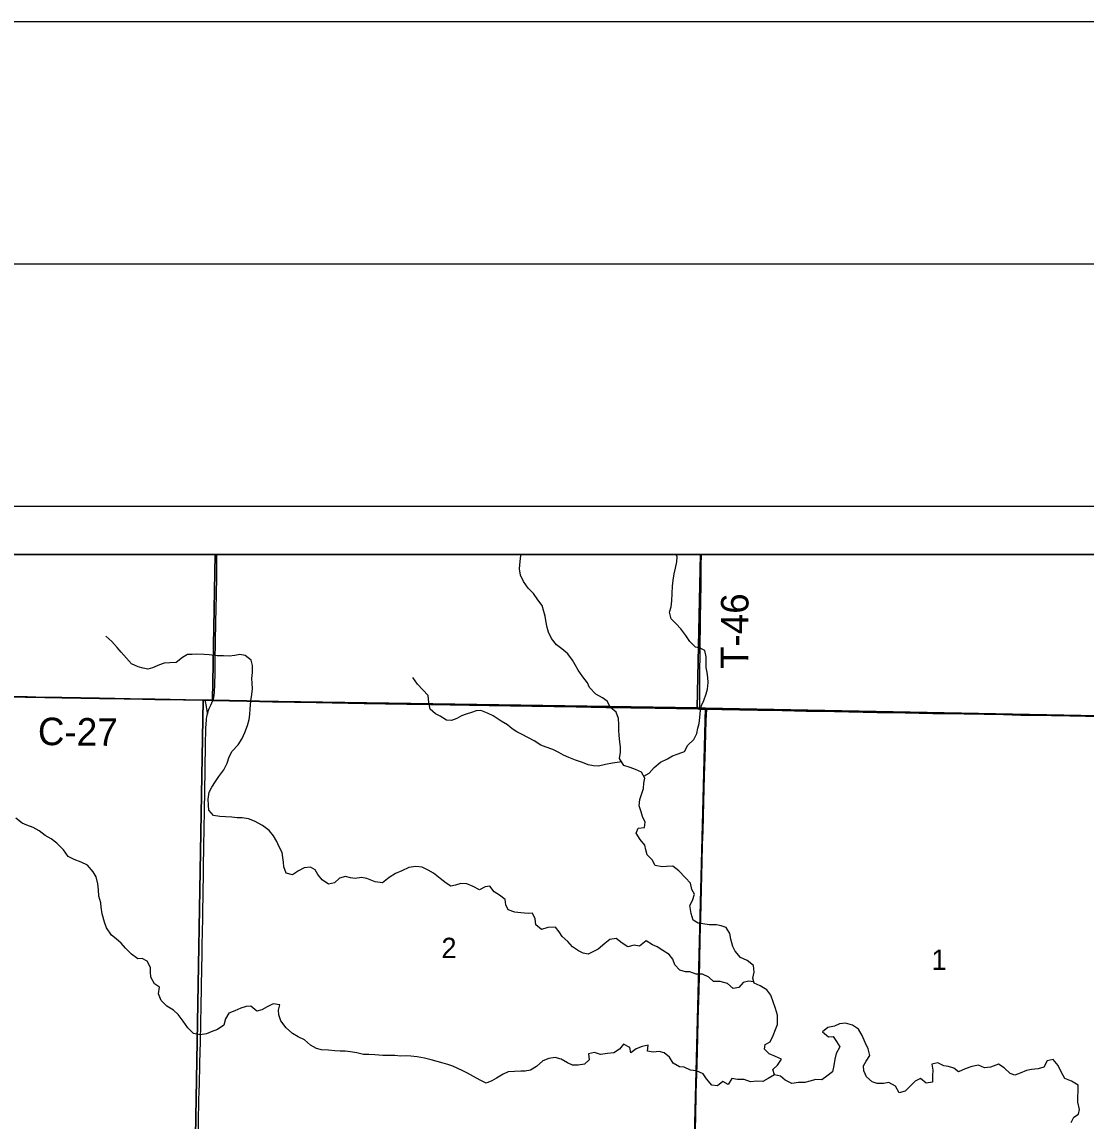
# Model space of a CAD drawing. Extents: x 0 to 34, y 0 to 22.
# Drawn here: x 3.417 to 5.615, y 19.729 to 22 of the extents above; entities that cross this region are included whole.
import ezdxf

# ---------------------------------------------------------------- set-up
doc = ezdxf.new("R2010")
doc.units = 0
for name, color, linetype in [('GM_X_Corporation', 7, 'Continuous'), ('GM_X_County_Road', 7, 'Continuous'), ('GM_X_County_Road_Text', 7, 'Continuous'), ('GM_X_Minor_River', 7, 'Continuous'), ('GM_X_Section_Text', 7, 'Continuous'), ('GM_X_State_Route', 7, 'Continuous'), ('GM_X_Township_Road', 7, 'Continuous'), ('GM_X_Township_Road_Text', 7, 'Continuous'), ('SH_Border', 7, 'Continuous'), ('SH_Cut_Line', 7, 'Continuous'), ('SH_Data', 7, 'Continuous')]:
    doc.layers.add(name, color=color, linetype=linetype)

msp = doc.modelspace()

# ---------------------------------------------------------------- linework, layer by layer
at = {"layer": 'GM_X_Corporation'}
for points in [[(8.9, 20.9), (2.1, 20.9), (2.1, 14.6217)], [(5.8292, 20.9), (2.1, 20.9)], [(5.742, 20.5637), (5.5822, 20.5668), (5.5443, 20.5675), (5.4809, 20.5688), (5.4448, 20.5696), (5.364, 20.5708), (5.2987, 20.5721), (5.2415, 20.573), (5.1837, 20.5739), (5.096, 20.5757), (5.0369, 20.5768), (4.9878, 20.5778), (4.9369, 20.5789), (4.8629, 20.5803), (4.8315, 20.5809), (4.8169, 20.5812), (4.8131, 20.5812), (4.7249, 20.583), (4.6236, 20.5845), (4.562, 20.5855), (4.47, 20.5869), (4.3823, 20.5883), (4.2611, 20.5904), (4.212, 20.5911), (4.1237, 20.5925), (4.0249, 20.5943), (3.9341, 20.5961), (3.8813, 20.5975), (3.8459, 20.5982), (3.8113, 20.5988), (3.7944, 20.5991), (3.7547, 20.5998), (3.6913, 20.6008), (3.6403, 20.6019), (3.5769, 20.6028), (3.4992, 20.6043), (3.4644, 20.6047), (3.4277, 20.6055), (3.3867, 20.6062)], [(3.3867, 20.6062), (3.4277, 20.6055), (3.4644, 20.6047), (3.4992, 20.6043), (3.5769, 20.6028), (3.6403, 20.6019), (3.6913, 20.6008), (3.7547, 20.5998), (3.7944, 20.5991), (3.8113, 20.5988), (3.8459, 20.5982), (3.8813, 20.5975), (3.9341, 20.5961), (4.0249, 20.5943), (4.1237, 20.5925), (4.212, 20.5911), (4.2611, 20.5904), (4.3823, 20.5883), (4.47, 20.5869), (4.562, 20.5855), (4.6236, 20.5845), (4.7249, 20.583), (4.8131, 20.5812), (4.8169, 20.5812), (4.8315, 20.5809), (4.8629, 20.5803), (4.9369, 20.5789), (4.9878, 20.5778), (5.0369, 20.5768), (5.096, 20.5757), (5.1837, 20.5739), (5.2415, 20.573), (5.2987, 20.5721), (5.364, 20.5708), (5.4448, 20.5696), (5.4809, 20.5688), (5.5443, 20.5675), (5.5822, 20.5668), (5.742, 20.5637)]]:
    msp.add_lwpolyline(points, dxfattribs=at)
for points in [[(3.8162, 20.9), (2.8176, 20.9), (2.8121, 20.6157), (3.7914, 20.5987), (3.8107, 20.5986)], [(4.8189, 20.9), (3.8162, 20.9), (3.8107, 20.5986), (4.8123, 20.5837)], [(5.8254, 20.9), (4.8189, 20.9), (4.8123, 20.5837), (4.829, 20.5833), (5.8164, 20.5638)], [(2.7647, 20.6164), (2.8121, 20.6157), (3.7914, 20.5987), (3.7742, 19.6197), (2.7554, 19.6589)], [(3.7914, 20.5987), (3.8107, 20.5986), (4.8123, 20.5837), (4.829, 20.5833), (4.8036, 19.5906), (3.7742, 19.6197)], [(4.829, 20.5833), (5.8164, 20.5638), (5.7981, 19.5979), (5.7974, 19.5584), (4.8036, 19.5906)]]:
    msp.add_lwpolyline(points, close=True, dxfattribs=at)
at = {"layer": 'GM_X_County_Road'}
for p, q in [((3.7946, 20.5986), (3.8116, 20.5982)), ((4.8171, 20.5806), (4.8317, 20.5803))]:
    msp.add_line(p, q, dxfattribs=at)
for points in [[(2.8134, 20.6157), (2.8344, 20.6154), (2.8729, 20.6147), (2.9127, 20.614), (2.963, 20.613), (3.0221, 20.6119), (3.0587, 20.6113), (3.1141, 20.6101), (3.1501, 20.6096), (3.216, 20.6086), (3.2614, 20.6078), (3.308, 20.6069), (3.3397, 20.6062), (3.3869, 20.6056), (3.428, 20.605), (3.4646, 20.6042), (3.4994, 20.6037), (3.5771, 20.6023), (3.6406, 20.6013), (3.6915, 20.6002), (3.7549, 20.5993), (3.7946, 20.5986)], [(3.7946, 20.5986), (3.7956, 20.5958), (3.7964, 20.5929), (3.797, 20.5897), (3.7976, 20.5853), (3.7982, 20.581), (3.7989, 20.577), (3.7998, 20.5728), (3.8004, 20.5705)], [(3.8116, 20.5982), (3.8461, 20.5977), (3.8816, 20.5969), (3.9344, 20.5955), (4.0251, 20.5937), (4.124, 20.592), (4.2122, 20.5906), (4.2613, 20.5898), (4.3826, 20.5877), (4.4702, 20.5863), (4.5622, 20.5849), (4.6238, 20.584), (4.7251, 20.5824), (4.8134, 20.5807), (4.8171, 20.5806)], [(4.8065, 19.6437), (4.8092, 19.7375), (4.8101, 19.7872), (4.8118, 19.8469), (4.8135, 19.9014), (4.8144, 19.9387), (4.8161, 19.9996), (4.8174, 20.0592), (4.8185, 20.1071), (4.8193, 20.1456), (4.8202, 20.1791), (4.8218, 20.2375), (4.8224, 20.2642), (4.8233, 20.3009), (4.8241, 20.3288), (4.826, 20.3891), (4.8275, 20.4425), (4.8283, 20.4817), (4.829, 20.5034), (4.8298, 20.5302), (4.8307, 20.5562), (4.8312, 20.5686), (4.8317, 20.5803)], [(4.8317, 20.5803), (4.8631, 20.5797), (4.9371, 20.5783), (4.9881, 20.5772), (5.0372, 20.5763), (5.0962, 20.5752), (5.1839, 20.5733), (5.2417, 20.5725), (5.2989, 20.5715), (5.3642, 20.5703), (5.445, 20.5691), (5.4811, 20.5682), (5.5445, 20.5669), (5.5824, 20.5662), (5.7422, 20.5631), (5.7721, 20.5624), (5.8193, 20.5613)]]:
    msp.add_lwpolyline(points, dxfattribs=at)
at = {"layer": 'GM_X_Minor_River'}
for points in [[(4.4629, 20.8304), (4.453, 20.8443), (4.4472, 20.8574), (4.4452, 20.87), (4.446, 20.8852), (4.4474, 20.8977), (4.4477, 20.9)], [(4.7019, 20.4418), (4.713, 20.4481), (4.7232, 20.46), (4.7364, 20.4707), (4.751, 20.4775), (4.7614, 20.4841), (4.7729, 20.488), (4.7859, 20.493), (4.793, 20.5061), (4.8051, 20.5179), (4.8111, 20.5303), (4.8136, 20.5409), (4.8161, 20.5507), (4.8176, 20.5628), (4.8191, 20.578), (4.8212, 20.5878), (4.8257, 20.5983), (4.8306, 20.6119), (4.8331, 20.6217), (4.8345, 20.6354), (4.8344, 20.6456), (4.8324, 20.6563), (4.8308, 20.6662), (4.8306, 20.6761), (4.8309, 20.6883), (4.8278, 20.7016), (4.8181, 20.706), (4.8083, 20.7082), (4.7972, 20.7199), (4.7887, 20.7322), (4.7784, 20.7462), (4.7677, 20.7571), (4.7585, 20.7668), (4.7546, 20.7806), (4.7583, 20.7919), (4.7594, 20.804), (4.7605, 20.8192), (4.7613, 20.8344), (4.7623, 20.8469), (4.7642, 20.8597), (4.7671, 20.8714), (4.7701, 20.885), (4.7704, 20.8953), (4.7685, 20.9)], [(4.9721, 19.8246), (4.9682, 19.8358), (4.9779, 19.8446), (4.9866, 19.857), (4.9742, 19.8626), (4.961, 19.8682), (4.951, 19.8776), (4.9528, 19.8874), (4.9628, 19.8929), (4.9692, 19.9064), (4.9737, 19.9188), (4.9781, 19.929), (4.9783, 19.9388), (4.9778, 19.9483), (4.9736, 19.9617), (4.9694, 19.9759), (4.964, 19.9897), (4.9559, 20.0002), (4.9425, 20.0089), (4.9297, 20.0145), (4.9273, 20.0244), (4.9295, 20.0369), (4.9287, 20.0506), (4.9153, 20.0612), (4.9014, 20.0673), (4.8907, 20.0804), (4.8856, 20.0901), (4.8815, 20.105), (4.8795, 20.1168), (4.8722, 20.1295), (4.8616, 20.1325), (4.8518, 20.1346), (4.8367, 20.135), (4.8238, 20.1368), (4.814, 20.1382), (4.8039, 20.1445), (4.7996, 20.1579), (4.797, 20.1747), (4.8026, 20.1852), (4.8067, 20.198), (4.8009, 20.2077), (4.7982, 20.2207), (4.7882, 20.2319), (4.7745, 20.2463), (4.7618, 20.2558), (4.7489, 20.2553), (4.7394, 20.2544), (4.7254, 20.2574), (4.7193, 20.269), (4.7089, 20.2795), (4.7057, 20.2898), (4.7041, 20.2994), (4.6945, 20.311), (4.6861, 20.3238), (4.6901, 20.3343), (4.7031, 20.3359), (4.7049, 20.3468), (4.6991, 20.3584), (4.6966, 20.3679), (4.6924, 20.3806), (4.6935, 20.3935), (4.698, 20.4063), (4.7013, 20.4161), (4.7015, 20.4275), (4.7041, 20.438), (4.6972, 20.45), (4.6848, 20.4556), (4.6739, 20.4597), (4.6607, 20.4638), (4.6519, 20.4785), (4.6534, 20.4917), (4.6537, 20.5024), (4.6524, 20.5123), (4.6508, 20.5264), (4.6503, 20.5359), (4.6502, 20.5488), (4.6498, 20.561), (4.6448, 20.574), (4.6329, 20.5838), (4.626, 20.5969), (4.6163, 20.604), (4.6028, 20.6115), (4.5895, 20.6251), (4.5852, 20.6347), (4.5756, 20.6471), (4.5661, 20.6611), (4.5603, 20.6718), (4.5545, 20.6815), (4.5449, 20.6943), (4.5326, 20.7048), (4.5215, 20.7131), (4.5112, 20.7263), (4.505, 20.7393), (4.5022, 20.7493), (4.5002, 20.7592), (4.4979, 20.7726), (4.4954, 20.7821), (4.4916, 20.7944), (4.4828, 20.806), (4.4736, 20.8195), (4.4629, 20.8304)], [(3.8504, 20.3568), (3.8372, 20.3579), (3.8258, 20.3585), (3.8129, 20.3607), (3.803, 20.3716), (3.8025, 20.3819), (3.8016, 20.3945), (3.8035, 20.4085), (3.8091, 20.419), (3.8169, 20.4309), (3.8236, 20.441), (3.8342, 20.4548), (3.841, 20.4687), (3.8448, 20.4815), (3.8515, 20.4935), (3.864, 20.5065), (3.8719, 20.5196), (3.8775, 20.532), (3.8828, 20.5467), (3.8865, 20.5591), (3.8875, 20.569), (3.8882, 20.58), (3.8897, 20.5978), (3.892, 20.6103), (3.8934, 20.622), (3.8929, 20.6338), (3.892, 20.6433), (3.8931, 20.6558), (3.893, 20.6703), (3.8903, 20.6814), (3.878, 20.6912), (3.867, 20.6933), (3.8568, 20.6913), (3.8453, 20.6897), (3.8332, 20.6904), (3.8203, 20.6907), (3.8036, 20.6923), (3.7934, 20.6933), (3.7786, 20.694), (3.7688, 20.6935), (3.7589, 20.6934), (3.7489, 20.6872), (3.7353, 20.6769), (3.7224, 20.6757), (3.7106, 20.6756), (3.7011, 20.672), (3.6869, 20.6659), (3.6769, 20.6631), (3.6671, 20.6649), (3.6569, 20.6674), (3.6434, 20.6742), (3.6331, 20.6859), (3.622, 20.6983), (3.6139, 20.708), (3.6028, 20.7204), (3.5905, 20.731)], [(4.6563, 20.4712), (4.6373, 20.4686), (4.6224, 20.4659), (4.6083, 20.4628), (4.5977, 20.4631), (4.5871, 20.4653), (4.5754, 20.4701), (4.5608, 20.4747), (4.5469, 20.4807), (4.5356, 20.4855), (4.5259, 20.4907), (4.5135, 20.4967), (4.4999, 20.5016), (4.489, 20.5061), (4.4752, 20.5148), (4.4636, 20.5208), (4.4494, 20.5287), (4.4396, 20.5335), (4.4299, 20.5399), (4.4202, 20.5481), (4.4071, 20.5556), (4.3907, 20.5663), (4.3787, 20.5719), (4.3652, 20.5776), (4.3557, 20.577), (4.3457, 20.5735), (4.335, 20.57), (4.3254, 20.5668), (4.3154, 20.5609), (4.3047, 20.557), (4.2941, 20.5573), (4.281, 20.566), (4.2713, 20.5708), (4.2601, 20.5806), (4.2578, 20.5939), (4.2563, 20.6084), (4.2341, 20.6317), (4.2249, 20.646)], [(3.7398, 19.9492), (3.7302, 19.9586), (3.716, 19.9669), (3.7049, 19.9786), (3.6991, 19.992), (3.7014, 20.0057), (3.6905, 20.0128), (3.6829, 20.0263), (3.6828, 20.0373), (3.6826, 20.0468), (3.6757, 20.0599), (3.6656, 20.0651), (3.6561, 20.0645), (3.6435, 20.074), (3.6309, 20.0864), (3.622, 20.0969), (3.6116, 20.1055), (3.6019, 20.1134), (3.5913, 20.1285), (3.5874, 20.1403), (3.5829, 20.1572), (3.5806, 20.1709), (3.5797, 20.1804), (3.5758, 20.1938), (3.575, 20.2071), (3.5738, 20.2197), (3.57, 20.2342), (3.5638, 20.2443), (3.5527, 20.2578), (3.5396, 20.2639), (3.5249, 20.2695), (3.5122, 20.2759), (3.5026, 20.2895), (3.4893, 20.3031), (3.477, 20.3121), (3.4647, 20.3193), (3.4528, 20.3291), (3.44, 20.3359), (3.4272, 20.3404), (3.4171, 20.3448), (3.4041, 20.3554)], [(4.9291, 20.0171), (4.9184, 20.0182), (4.9073, 20.0154), (4.8984, 20.0054), (4.8862, 20.0034), (4.8747, 20.0136), (4.8596, 20.0178), (4.8459, 20.0174), (4.8359, 20.0267), (4.8231, 20.0327), (4.8102, 20.0331), (4.7971, 20.0376), (4.7876, 20.0378), (4.7759, 20.0411), (4.7659, 20.052), (4.762, 20.0635), (4.7539, 20.0732), (4.7408, 20.0819), (4.7296, 20.0894), (4.7195, 20.0931), (4.7068, 20.1014), (4.6932, 20.0907), (4.6819, 20.0925), (4.6689, 20.0894), (4.657, 20.0969), (4.645, 20.1063), (4.6313, 20.1044), (4.6213, 20.0959), (4.6077, 20.0845), (4.5977, 20.0794), (4.5869, 20.074), (4.5764, 20.0761), (4.5666, 20.0813), (4.5543, 20.0892), (4.5451, 20.1005), (4.5328, 20.1107), (4.5266, 20.1203), (4.5193, 20.13), (4.5037, 20.1292), (4.4907, 20.1254), (4.4784, 20.1344), (4.4775, 20.147), (4.4721, 20.1585), (4.4626, 20.1584), (4.4479, 20.1595), (4.435, 20.161), (4.4215, 20.1659), (4.4168, 20.1759), (4.4151, 20.1869), (4.4036, 20.1959), (4.3928, 20.2031), (4.3836, 20.2147), (4.374, 20.213), (4.3621, 20.2069), (4.349, 20.2136), (4.3359, 20.2193), (4.3234, 20.22), (4.313, 20.2164), (4.3031, 20.2148), (4.2934, 20.2211), (4.2807, 20.2305), (4.2673, 20.2411), (4.2565, 20.2479), (4.2437, 20.2535), (4.2305, 20.2553), (4.216, 20.2531), (4.2018, 20.2466), (4.1888, 20.2408), (4.1757, 20.2328), (4.1617, 20.2217), (4.1466, 20.2236), (4.1293, 20.2305), (4.1183, 20.2323), (4.1054, 20.2304), (4.0956, 20.2317), (4.0854, 20.2347), (4.0728, 20.2308), (4.0627, 20.2212), (4.0501, 20.2188), (4.0374, 20.2275), (4.0285, 20.2384), (4.0231, 20.248), (4.0134, 20.2536), (3.9997, 20.2524), (3.9885, 20.2466), (3.9758, 20.2382), (3.9626, 20.2415), (3.958, 20.2542), (3.9575, 20.2644), (3.9562, 20.274), (3.9545, 20.2843), (3.948, 20.297), (3.9433, 20.3066), (3.9368, 20.3185), (3.9275, 20.3294), (3.9138, 20.3396), (3.8977, 20.3488), (3.8849, 20.3536), (3.8717, 20.3559), (3.8618, 20.3561), (3.8504, 20.3568)], [(4.8651, 19.811), (4.8543, 19.8018), (4.8425, 19.8032), (4.8315, 19.8164), (4.8241, 19.8268), (4.811, 19.8332), (4.7981, 19.8347), (4.785, 19.8403), (4.7752, 19.8413), (4.7624, 19.8489), (4.7552, 19.8612), (4.7436, 19.8702), (4.7338, 19.8731), (4.7213, 19.8719), (4.7095, 19.8737), (4.711, 19.8859), (4.6984, 19.8831), (4.6861, 19.8785), (4.6749, 19.8701), (4.6729, 19.8815), (4.6598, 19.8879), (4.6519, 19.8775), (4.6396, 19.8702), (4.6271, 19.869), (4.6126, 19.867), (4.5998, 19.8708), (4.5876, 19.8684), (4.5892, 19.8555), (4.5795, 19.8466), (4.5661, 19.8447), (4.5547, 19.8449), (4.5442, 19.8498), (4.5311, 19.8569), (4.5183, 19.8603), (4.5057, 19.8587), (4.4935, 19.8537), (4.4803, 19.8419), (4.4676, 19.8342), (4.4569, 19.8322), (4.4474, 19.8324), (4.4216, 19.8308), (4.4112, 19.8265), (4.3977, 19.8181), (4.3877, 19.8123), (4.3762, 19.8076), (4.3635, 19.814), (4.3496, 19.8212), (4.3376, 19.8283), (4.3279, 19.8331), (4.3174, 19.838), (4.3069, 19.8424), (4.2967, 19.8464), (4.2869, 19.849), (4.2748, 19.8523), (4.2624, 19.856), (4.2488, 19.859), (4.2337, 19.8617), (4.2201, 19.8636), (4.2106, 19.8638), (4.1988, 19.8637), (4.1871, 19.8644), (4.1628, 19.865), (4.1461, 19.8658), (4.1336, 19.8669), (4.1223, 19.8671), (4.1087, 19.8705), (4.0958, 19.8724), (4.0848, 19.8734), (4.0746, 19.8736), (4.0636, 19.8743), (4.05, 19.8758), (4.036, 19.8765), (4.0258, 19.8794), (4.013, 19.8858), (4.0004, 19.8971), (3.9877, 19.9035), (3.9757, 19.9103), (3.9627, 19.922), (3.9517, 19.9364), (3.9478, 19.949), (3.9473, 19.9585), (3.9498, 19.9695), (3.9362, 19.9713), (3.9235, 19.9652), (3.9124, 19.959), (3.9024, 19.9566), (3.8898, 19.9664), (3.8803, 19.9659), (3.8692, 19.9623), (3.8565, 19.957), (3.8446, 19.9523), (3.8375, 19.9407), (3.8338, 19.9275), (3.8207, 19.9187), (3.808, 19.9137), (3.7984, 19.9098), (3.7851, 19.9075), (3.7715, 19.9101), (3.76, 19.9218), (3.7497, 19.9357), (3.7398, 19.9492)], [(5.5849, 19.7261), (5.5901, 19.7374), (5.6001, 19.7436), (5.6019, 19.7534), (5.5988, 19.7683), (5.5987, 19.7808), (5.5994, 19.7907), (5.5993, 19.8036), (5.5855, 19.8116), (5.5719, 19.8172), (5.5647, 19.8299), (5.5582, 19.8442), (5.5475, 19.8566), (5.5349, 19.8539), (5.5285, 19.8407), (5.5163, 19.8369), (5.5029, 19.8357), (5.4926, 19.834), (5.4792, 19.8279), (5.4685, 19.8244), (5.4587, 19.8273), (5.4465, 19.8394), (5.4349, 19.8465), (5.4184, 19.8408), (5.4055, 19.8396), (5.3931, 19.8449), (5.3797, 19.8418), (5.3656, 19.8372), (5.3521, 19.8307), (5.3425, 19.8386), (5.3315, 19.8419), (5.3217, 19.8433), (5.309, 19.8493), (5.2967, 19.8465), (5.2991, 19.8343), (5.2981, 19.8237), (5.2985, 19.8096), (5.2855, 19.8077), (5.2736, 19.8171), (5.2625, 19.8117), (5.2516, 19.8009), (5.2419, 19.7913), (5.2293, 19.7878), (5.222, 19.8013), (5.2082, 19.8092), (5.1971, 19.8072), (5.1838, 19.8068), (5.1736, 19.8101), (5.1618, 19.8207), (5.1564, 19.8333), (5.1555, 19.8436), (5.1614, 19.8533), (5.1685, 19.8649), (5.1651, 19.8783), (5.1593, 19.8914), (5.1532, 19.906), (5.1452, 19.9191), (5.1329, 19.9274), (5.1186, 19.9315), (5.1064, 19.9299), (5.0956, 19.9256), (5.0823, 19.9229), (5.0711, 19.9133), (5.0837, 19.9035), (5.0932, 19.9037), (5.0998, 19.8936), (5.1071, 19.8828), (5.0992, 19.8686), (5.0962, 19.8572), (5.0944, 19.844), (5.0914, 19.8308), (5.0802, 19.8219), (5.0694, 19.8146), (5.0569, 19.8153), (5.0446, 19.8118), (5.0343, 19.809), (5.0214, 19.809), (5.0077, 19.807), (4.9942, 19.8138), (4.9845, 19.8217), (4.9721, 19.8246), (4.959, 19.817), (4.9479, 19.8112), (4.935, 19.8119), (4.922, 19.8103), (4.9092, 19.8152), (4.8952, 19.8155), (4.8835, 19.817), (4.8764, 19.805), (4.8651, 19.811)]]:
    msp.add_lwpolyline(points, dxfattribs=at)
at = {"layer": 'GM_X_State_Route'}
for points in [[(3.8116, 20.5982), (3.8125, 20.6012), (3.8131, 20.6034), (3.8137, 20.6062), (3.8141, 20.6084), (3.8148, 20.6153), (3.8155, 20.6308), (3.816, 20.6557), (3.8162, 20.6805), (3.8169, 20.7191), (3.8176, 20.7601), (3.8186, 20.8166), (3.8193, 20.8545), (3.8198, 20.9)], [(3.7909, 20.1669), (3.7914, 20.1928), (3.793, 20.3034), (3.7934, 20.327), (3.7943, 20.3767), (3.7949, 20.4059), (3.7957, 20.4592), (3.7964, 20.5052), (3.797, 20.5412), (3.7974, 20.5498), (3.798, 20.5572), (3.7985, 20.5605), (3.7991, 20.5645), (3.8004, 20.5705), (3.8007, 20.5717), (3.8014, 20.5747), (3.8025, 20.578), (3.8038, 20.5816), (3.8055, 20.5856), (3.807, 20.5888), (3.8092, 20.5933), (3.8116, 20.5982)], [(3.7834, 19.7947), (3.7835, 19.8018), (3.7847, 19.849), (3.7858, 19.8937), (3.7874, 19.9677), (3.788, 20.0035), (3.7886, 20.0493), (3.7891, 20.0679), (3.7895, 20.0928), (3.7905, 20.148), (3.7909, 20.1669)], [(3.7791, 19.5842), (3.7795, 19.6029), (3.7797, 19.6154), (3.7807, 19.6601), (3.7811, 19.6862), (3.782, 19.731), (3.7827, 19.7683), (3.7834, 19.7947)]]:
    msp.add_lwpolyline(points, dxfattribs=at)
at = {"layer": 'GM_X_Township_Road'}
msp.add_lwpolyline([(4.8171, 20.5806), (4.8172, 20.5837), (4.8173, 20.5874), (4.8175, 20.6203), (4.8178, 20.6514), (4.8183, 20.6999), (4.8189, 20.767), (4.8194, 20.8037), (4.82, 20.8373), (4.8205, 20.877), (4.8208, 20.9)], dxfattribs=at)
at = {"layer": 'SH_Border'}
msp.add_lwpolyline([(1.5, 21.5), (33.5, 21.5), (33.5, 0.5), (1.5, 0.5)], close=True, dxfattribs=at)
at = {"layer": 'SH_Cut_Line'}
msp.add_lwpolyline([(0, 0), (34, 0), (34, 22), (0, 22)], close=True, dxfattribs=at)
at = {"layer": 'SH_Data'}
for p, q in [((2, 21), (9, 21)), ((2.1, 20.9), (8.9, 20.9))]:
    msp.add_line(p, q, dxfattribs=at)

# ---------------------------------------------------------------- texts
at = {"layer": 'GM_X_County_Road_Text'}
msp.add_text('C-27', height=0.05682, rotation=359.313, dxfattribs=at).set_placement((3.4496, 20.5062))
at = {"layer": 'GM_X_Section_Text'}
for s, p in [('2', (4.2837, 20.0661)), ('1', (5.2962, 20.0417))]:
    msp.add_text(s, height=0.0419, rotation=0, dxfattribs=at).set_placement(p)
at = {"layer": 'GM_X_Township_Road_Text'}
msp.add_text('T-46', height=0.05682, rotation=89.6535, dxfattribs=at).set_placement((4.9173, 20.6632))

doc.saveas('drawing.dxf')
